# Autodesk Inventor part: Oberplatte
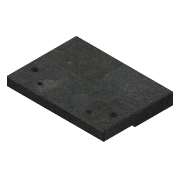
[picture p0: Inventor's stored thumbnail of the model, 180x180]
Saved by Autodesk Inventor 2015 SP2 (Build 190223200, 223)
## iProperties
Created: 2017-07
Material: St
Document SubType Name: Modeling
Designer: UR
Density: 7.85 g/cm^3
Appearance: Platte
Mass: 722.659 g
Surface Area: 205.654 cm^2
Volume: 92.0585 cm^3
Part Number: Oberplatte
Project: Projekt Locher
Author: UR
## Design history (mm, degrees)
sketch "Skizze1"
  geometry: L1 (-50, 72)-(50, 72); L2 (50, 72)-(50, 0); L3 (50, 0)-(-50, 0); L4 (-50, 0)-(-50, 72); 2 further points
  constraints: 8 end point, 2 parallel, 1 coincident, 1 horizontal, 1 midpoint, 1 perpendicular
  dimensions: "d0" = 100 distance of L1.start L1.end; "d1" = 72 distance of L3.end L1.start
extrude "Grundkörper" new body sketch "Skizze1" distance "d2" = 12; taper "d3" = 0 deg
node "Mittelebene yz"
sketch "Skizze für Bohrungen"
  geometry: L1 (0, 0)-(0, 107.835); L2 (50, 72)-(-50, 72) reference; 10 further points
  constraints: 5 symmetric about line, 3 vertical alignment, 2 end point, 1 vertical
  dimensions: "d5" = 52 distance from line of L2 point (-40, 20); "d16" = 16 distance of point (40, 20) point (40, 36); "d17" = 16 distance of point (40, 36) point (40, 52); "d18" = 16 distance of point (40, 52) point (40, 68); "d52" = 50 distance of point (25, 10) point (-25, 10); "d53" = 80 distance of point (40, 20) point (-40, 20); "d54" = 10 vertical distance of point (40, 20) point (25, 10)
hole "Bohrung für Stanzmatrize" sketch "Skizze für Bohrungen" diameter "d6" = 6.1; stored, may be unused: countersink angle "d10" = 90 deg, drill point angle "d12" = 118 deg; dims "d7" = 6, "d8" = 4, "d9" = 2, "d11" = 8
hole "Gewindebohrung zur Grundplatte" sketch "Skizze für Bohrungen" diameter "d19" = 3.242; stored, may be unused: countersink angle "d23" = 90 deg, drill point angle "d25" = 118 deg; dims "d20" = 6, "d21" = 4, "d22" = 2, "d24" = 8
hole "Bohrung für Zylinderstifte" sketch "Skizze für Bohrungen" diameter "d26" = 4; stored, may be unused: countersink angle "d30" = 82 deg, drill point angle "d32" = 118 deg; dims "d27" = 8, "d28" = 3.023, "d29" = 2, "d31" = 8
hole "Bohrung zur Säule" sketch "Skizze für Bohrungen" diameter "d38" = 4.5; stored, may be unused: countersink angle "d42" = 82 deg, drill point angle "d44" = 118 deg; dims "d39" = 8, "d40" = 3.023, "d41" = 2, "d43" = 6
sketch "Skizze3"
  geometry: L1 (-50, 0)-(-50, 72) reference; L2 (50, 0)-(-50, 0); L3 (-50, 0)-(-50, 32); L4 (-50, 32)-(50, 32); L5 (50, 32)-(50, 0); C1 r 3.05 at (-40, 20) reference; 1 further point
  constraints: 8 end point, 2 parallel, 1 horizontal, 1 perpendicular, 1 point on line
  dimensions: "d13" = 12 distance from line of L4 C1.centre
extrude "Ausklinkung für Papierstapel" cut sketch "Skizze3" distance "d14" = 2; taper "d15" = 0 deg
sketch "Skizze4"
  geometry: C1 r 2.25 at (25, 10) reference; C2 r 2.25 at (25, 10) reference; C3 r 2.25 at (-25, 10) reference; 1 further point
hole "Senkung für Zylinderschraube" sketch "Skizze4" at (25, 10), (-25, 10) diameter "d45" = 8; stored, may be unused: countersink angle "d49" = 82 deg, drill point angle "d51" = 0 deg; dims "d46" = 8, "d47" = 3.023, "d48" = 2, "d50" = 4.4
chamfer "Fase2" distance "d68" = 1; stored, may be unused: second distance "d69" = 2, angle "d70" = 45 deg
sketch "Skizze10"
  geometry: L1 (-0.5, 0)-(0, 0.5); L2 (0, 0.5)-(0.5, 0); L3 (0.5, 0)-(-0.5, 0); L4 (0, 0)-(0, 0.5); L5 (-49, 0)-(49, 0) reference; 1 further point
  constraints: 8 end point, 2 midpoint, 1 horizontal, 1 perpendicular, 1 vertical
  dimensions: "d71" = 1 distance of L2.end L1.start
extrude "Mittelmarke" cut sketch "Skizze10" stored distance "d72" = 10; taper "d73" = 0 deg
sketch "Skizze8"
  geometry: C1 r 2.25 at (25, 10) reference; C2 r 2.25 at (-25, 10) reference; 1 further point
hole "Senkung für Säule" sketch "Skizze8" at (-25, 10), (25, 10) diameter "d55" = 12; stored, may be unused: countersink angle "d59" = 82 deg, drill point angle "d61" = 0 deg; dims "d56" = 8, "d57" = 3.023, "d58" = 2, "d60" = 1
sketch "Skizze9"
  geometry: L1 (-15, 32)-(-13, 32) reference; L2 (-13, 32)-(-13, 0) reference; L3 (-13, 0)-(0, 0) reference; L4 (0, 72)-(0, 0) reference; L5 (-12, 72)-(0, 72) reference; L6 (-15, 32)-(-12, 72) reference; L7 (0, 0)-(-3, 72); L8 (-12, 72)-(0, 72) reference; 1 further point
  constraints: 2 end point, 1 point on line
  dimensions: "d64" = 12 distance from line of L6 L7.end
extrude "Abschrägung" sketch "Skizze9" stored distance "d65" = 0; taper "d66" = 0 deg
chamfer "Fase1" distance "d33" = 1; stored, may be unused: second distance "d34" = 2, angle "d35" = 45 deg
node "Volumenkörper1"
node "Projizierte Kontur1"
node "Projizierte Kontur2"
